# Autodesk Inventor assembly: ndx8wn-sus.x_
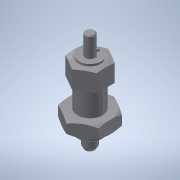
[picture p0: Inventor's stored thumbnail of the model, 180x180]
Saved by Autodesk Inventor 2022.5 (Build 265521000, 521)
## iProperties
Part Number: ndx8wn-sus.x_
Material: 一般
Document SubType Name: Assembly
Designer: ImaoCorp
Sending System: SOLIDWORKS 2017-2017317
MC: AMD64
MC_MODEL: Intel64 Family 6 Model 60 Stepping 3, GenuineIntel
OS: Windows_NT
FRU: Parasolid Version 29.0, build 201,  4-17-2017
FORMAT: text
GUISE: transmit
KEY: ndx8wn-sus
FILE: ndx8wn-sus.x_t
DATE: Wed Sep 04 15:30:23 2019
Author: ImaoCorp
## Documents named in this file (3)
- X:\14_SW2022-Inv2022\00_全2023-1023新製品(TCC)まで\n\ndx8wn-sus\NDX8WN-SUS.iam
- X:\14_SW2022-Inv2022\00_全2023-1023新製品(TCC)まで\n\ndx8wn-sus\ndx8wn-sus_01.ipt
- X:\14_SW2022-Inv2022\00_全2023-1023新製品(TCC)まで\n\ndx8wn-sus\ndx8wn-sus_02.ipt
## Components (2 placed, 2 different names)
1. ndx8wn-sus_01
2. ndx8wn-sus_02
